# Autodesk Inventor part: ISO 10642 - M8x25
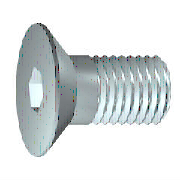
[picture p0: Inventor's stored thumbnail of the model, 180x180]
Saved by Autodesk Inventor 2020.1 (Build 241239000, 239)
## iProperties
Created: 2019-01
Part Number: ISO 10642 - M8x25
Material: Stahl, weich
Description: Senkschrauben mit Innensechskant
Document SubType Name: Modeling
Standard: ISO 10642
Designer: lutzd
Standards Organization: ISO
Language: de-DE
Size Designation: M8x25
Categories: <MemberInstance><Categories><Category DisplayName="Verbindungselemente" InternalName="e4da775c-781d-43d5-af7c-5136215cf5a6" Mnemonic="FSTN"><Category DisplayNam
Mass: 11.8122 g
Surface Area: 10.5283 cm^2
Volume: 1.50474 cm^3
Density: 7.85 g/cm^3
Appearance: Halbpoliert
IsCustomPart: 0
Author: lutzd
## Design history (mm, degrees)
node "WorkPoint1"
sketch "Skizze2"
  geometry: L1 (-4, -25)-(0, -25); L2 (-4, -4.4)-(-4, -25); L3 (-8, -0.4)-(-4, -4.4); L4 (-8, 0)-(-8, -0.4); L5 (0, 0)-(-8, 0); L6 (0, -25)-(0, 0); L7 (0, -25)-(0, 0); L8 (0, -30)-(0, 5) reference; L9 (1.6, 0)-(-9.6, 0) reference
  constraints: 14 end point, 3 vertical, 2 horizontal
  dimensions: "d3" = 8 distance of L5.start L4.start (= 0.5 x dk); "d5" = 4 distance of L1.start L1.end (= 0.5 x NND); "d7" = 25 distance of L1.end L5.start (= NLG); "ParC" = 0.4 distance of L4.start L3.start; "d22" = 0 distance between parallel lines of L8 L6; "d23" = 0 distance between parallel lines of L9 L5; "d43" = 45 deg angle of L6 L3 (= 0.5 x ang)
revolve "Drehung1" stored, may be unused: angle "d8" = 360 deg
node "MSC_A1"
node "MSC_PF1"
node "MSC_PT1"
body "Solid1"
node "Skizze1"
sketch "Skizze3"
  geometry: L1 (-2.5, 1.443)-(-2.5, -1.443); L2 (0, 2.887)-(-2.5, 1.443); L3 (2.5, 1.443)-(0, 2.887); L4 (2.5, -1.443)-(2.5, 1.443); L5 (0, -2.887)-(2.5, -1.443); L6 (-2.5, -1.443)-(0, -2.887); C1 r 2.5 at (0, 0); C2 r 4 at (0, 0) reference
  constraints: 12 end point, 6 tangent, 2 parallel, 2 vertical, 1 centre point, 1 concentric
  dimensions: "d11" = 5 diameter of C1 (= ParS); "d13" = 120 deg angle of L1 L2; "d15" = 120 deg angle of L6 L1
extrude "Extrusion1" cut sketch "Skizze3" distance "d16" = 3.5 (= ParT); taper "d17" = 0 deg
fillet "Rundung1" dims "d18" = 0.5 (= r)
chamfer "Fase1" distance "d19" = 0.625 (= 0.5 x PTC); stored, may be unused: angle "d20" = 45 deg, second distance "d39" = 0.625 (= 0.5 x PTC)
feature "Gewinde1" dims "d35" = 0, "b" = 18.1
other parameters: "NND" = 8 [user parameter; used in 2 equation terms], "PTC" = 1.25 [user parameter; used in 2 equation terms], "dk" = 16 [user parameter; used in 1 equation term], "ParK" = 4.4 [user parameter], "ParS" = 5 [user parameter; used in 1 equation term], "ParT" = 3.5 [user parameter; used in 1 equation term], "r" = 0.5 [user parameter; used in 1 equation term], "NLG" = 25 [user parameter; used in 1 equation term], "d0" = 45 deg (derived), "d2" = 3 (derived), "d4" = 1.5 (derived), "d6" = 8 (derived), "d9" = 0, "d10" = 2 (derived), "d12" = 120 deg (derived), "d14" = 120 deg (derived), "d37" = 0, "d38" = 0, "d40" = 0, "d41" = 0, "d42" = 0, "ang" = 90 deg [user parameter; used in 1 equation term], "THREADDIA" = 8 (= NND) [user parameter]
